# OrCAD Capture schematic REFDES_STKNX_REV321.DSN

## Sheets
1 P01 - Index: title: STKNX reference design; rev: 321; company: STMicroelectronics; note: Block diagram; note: 10 rue de Jouanet; note: 35700 Rennes, FR
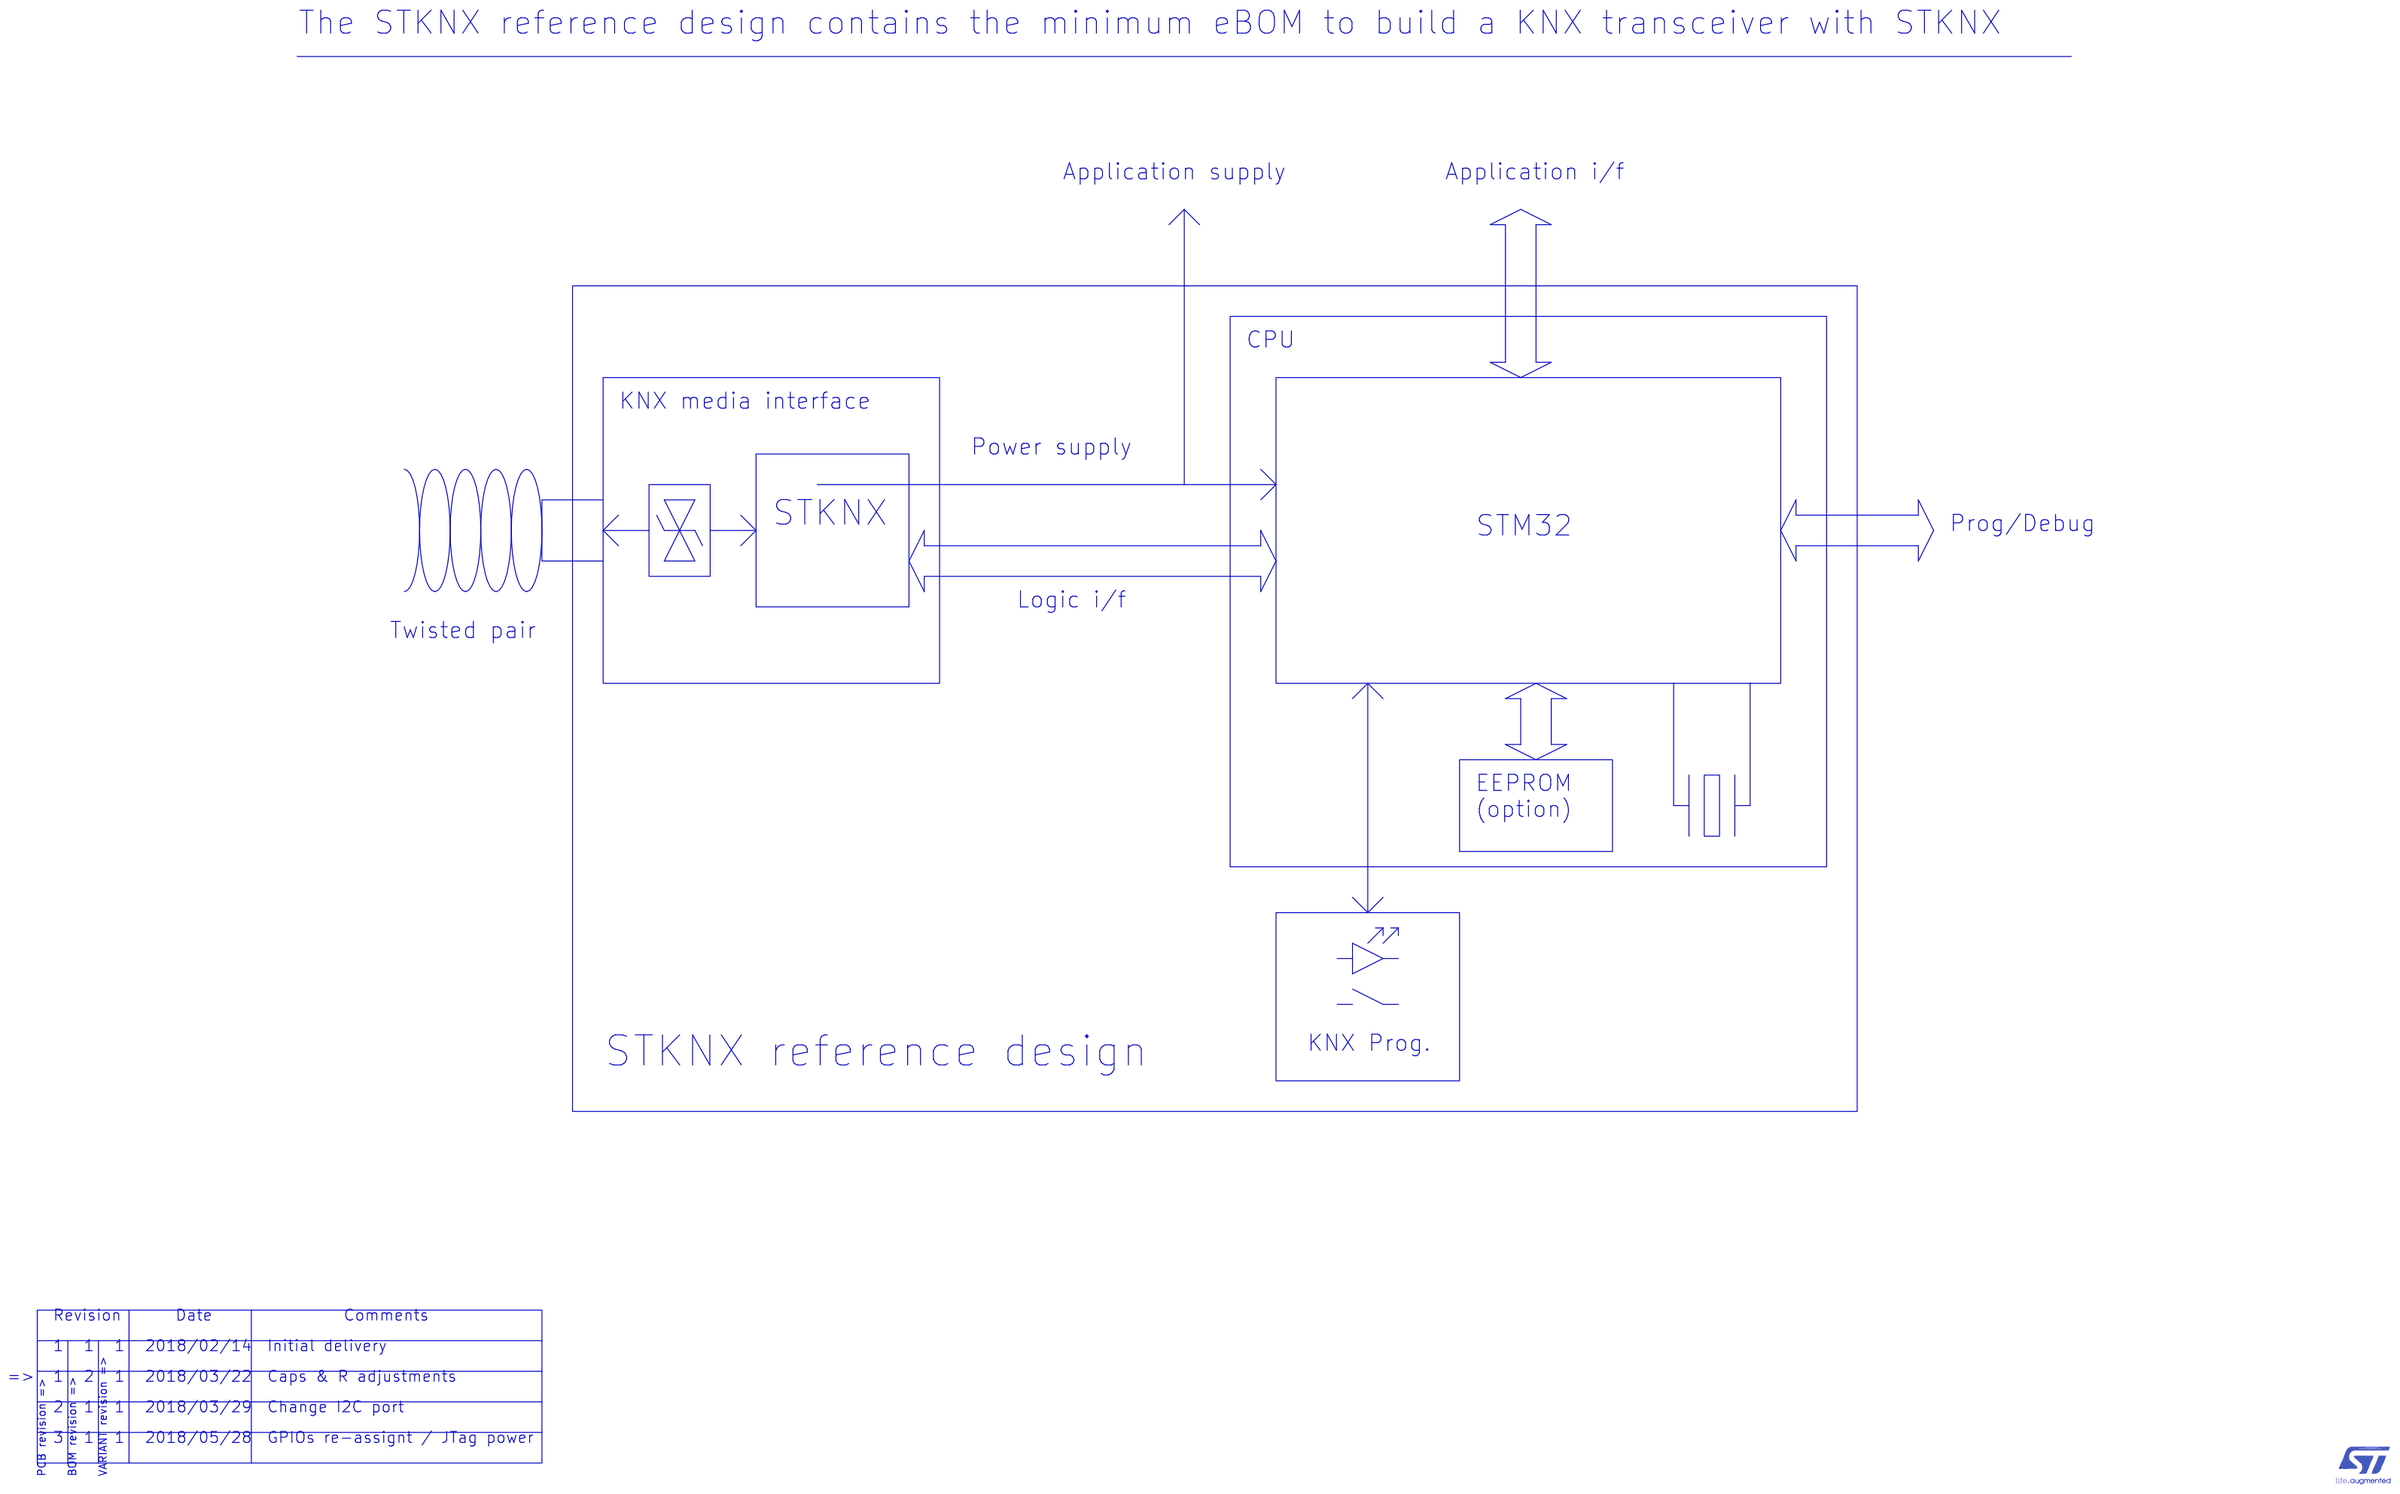
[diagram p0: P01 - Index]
2 P02 - STKNX: size A3; note: STKNX
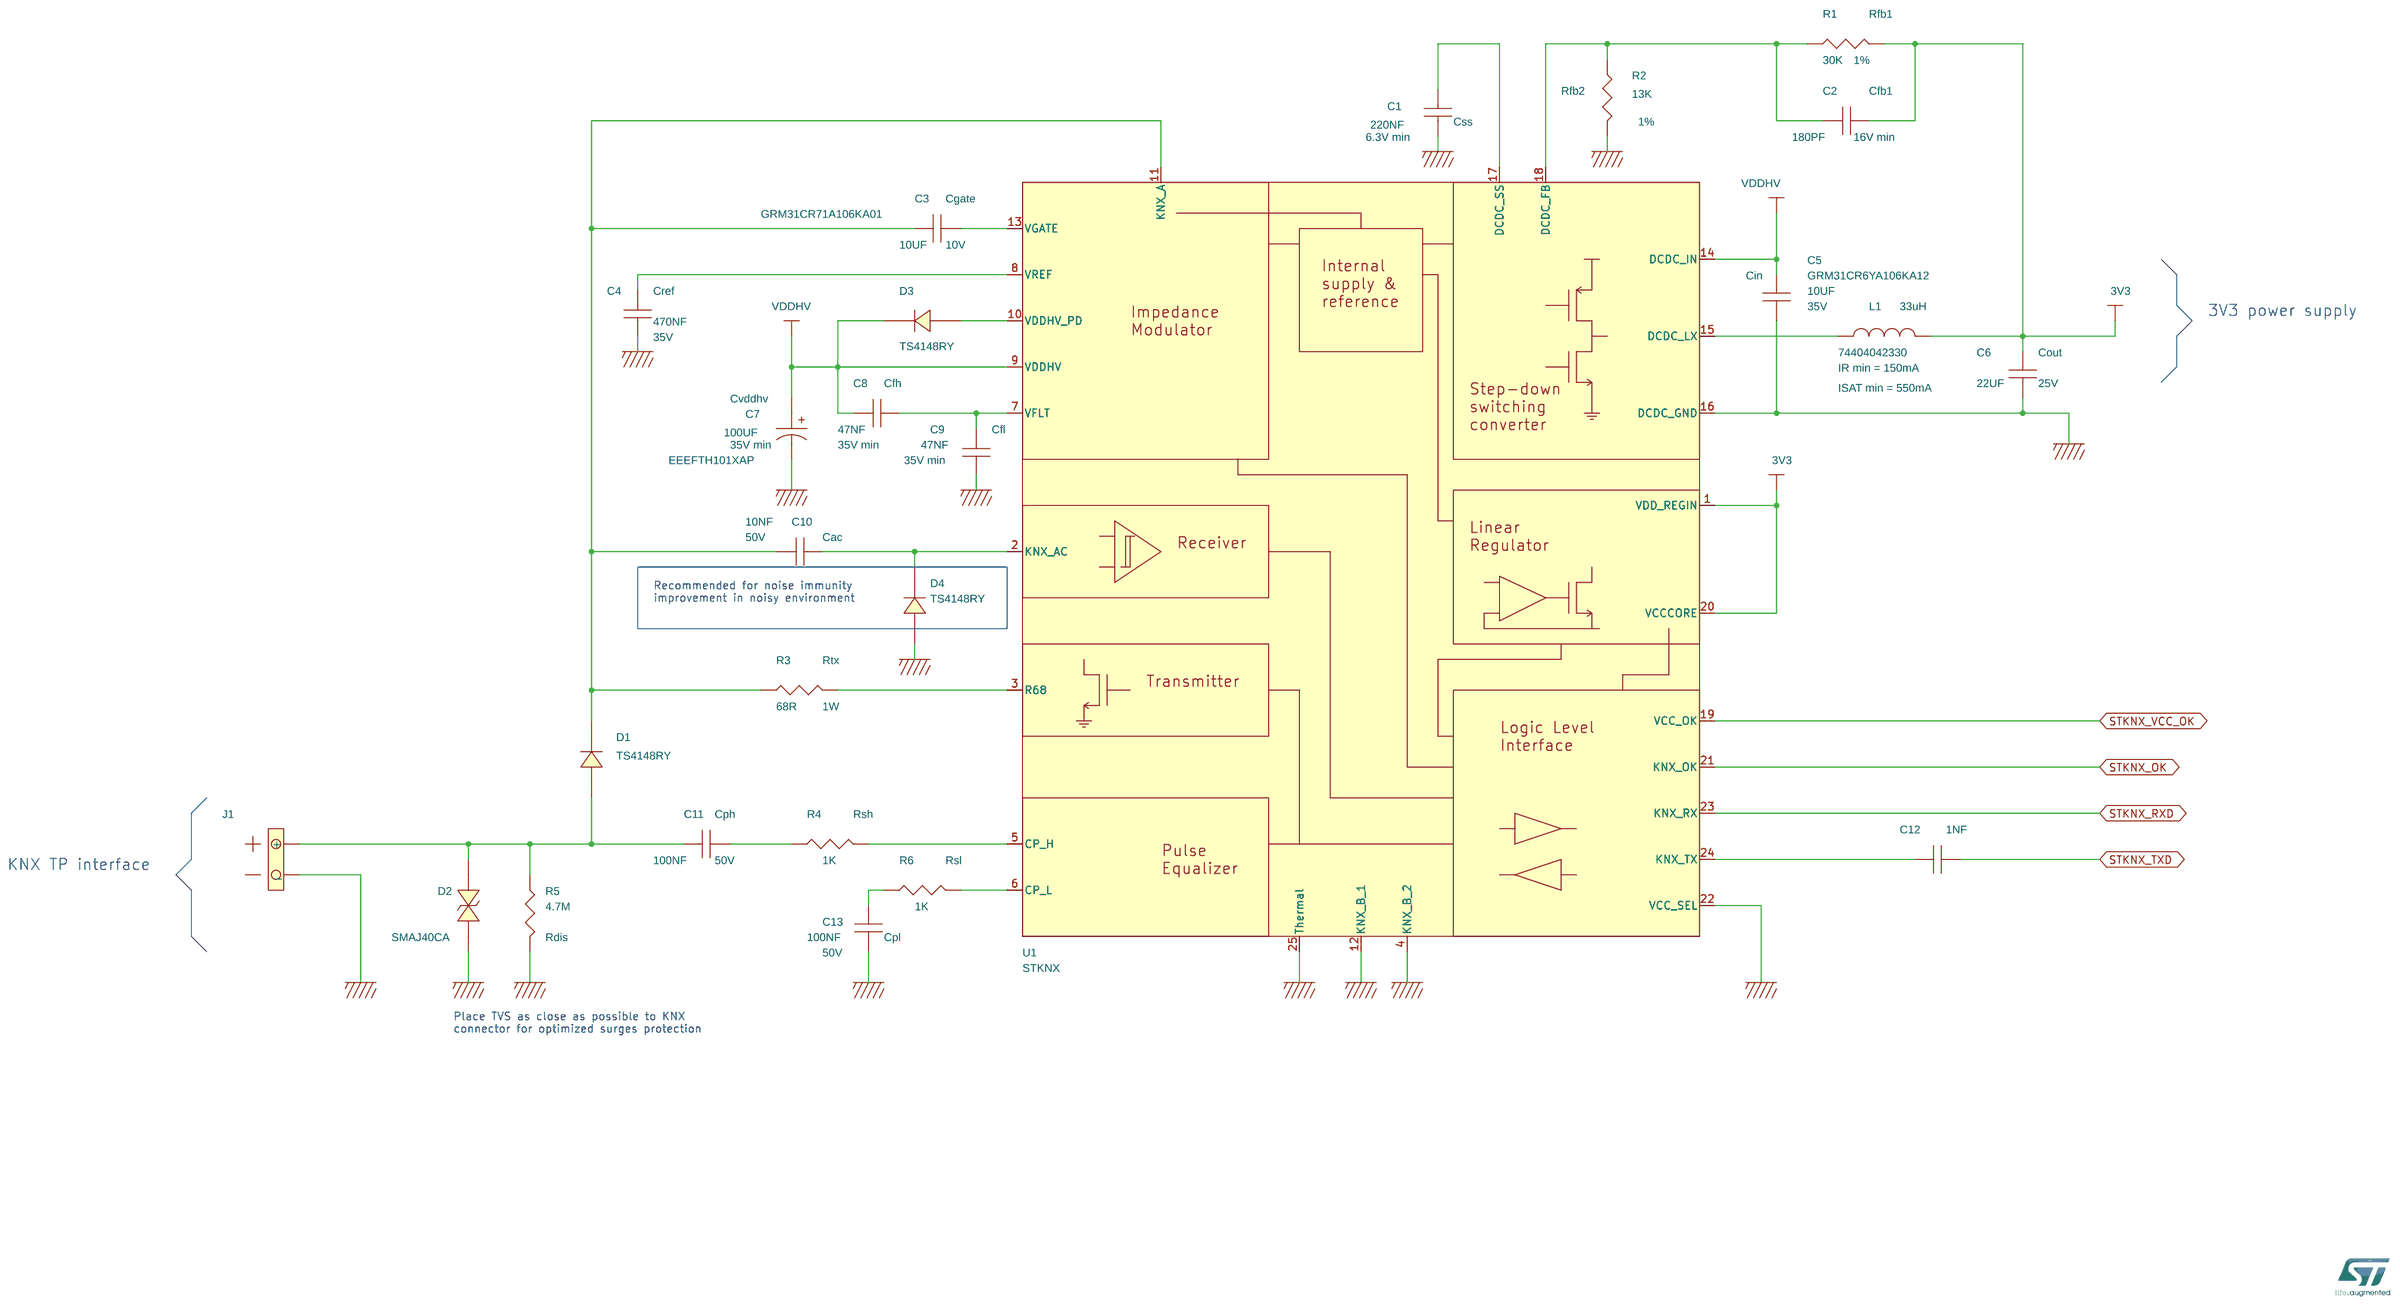
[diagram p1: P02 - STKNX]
3 P03 - CPU: size A3; note: CPU
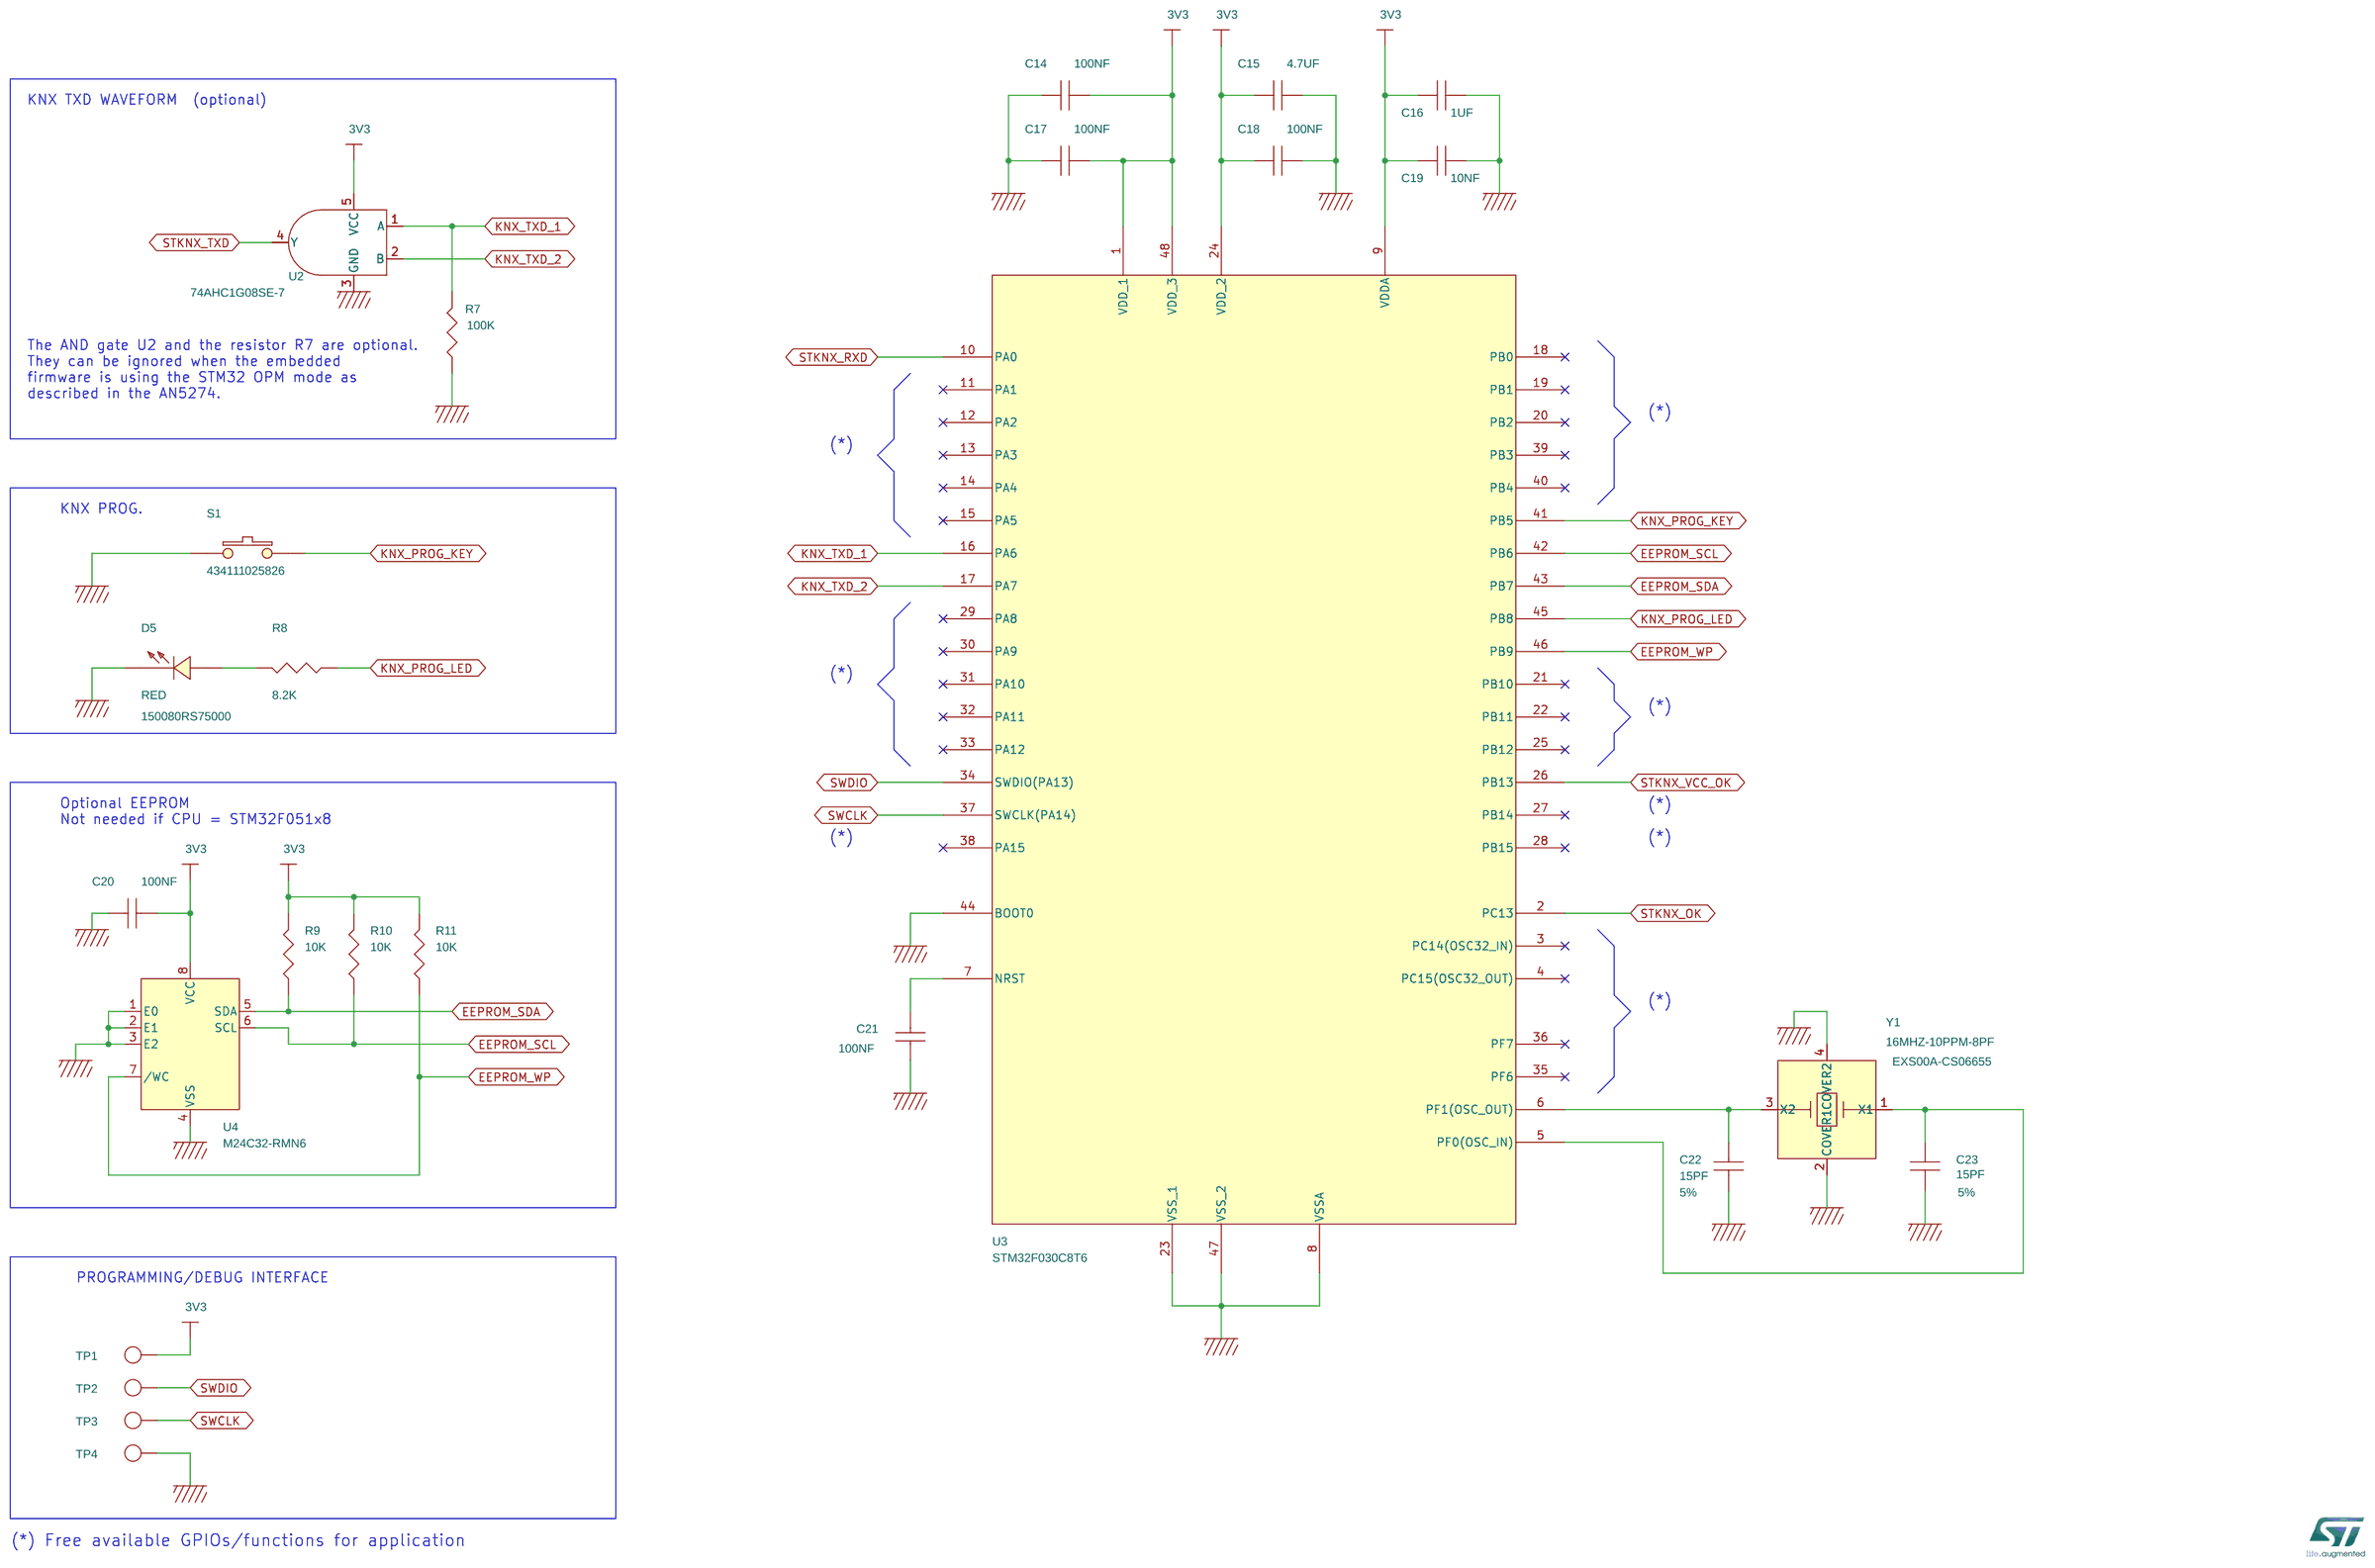
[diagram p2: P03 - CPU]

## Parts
sheet P02 - STKNX
C1  220NF  [0402]
C2  180PF  [0402]
C3  10UF  [1206]
C4  470NF  [0402]
C5  10UF  [1206]
C6  22UF  [1206]
C7  100UF  [D6.3_H7.7]
C8  47NF  [0402]
C9  47NF  [0402]
C10  10NF  [0402]
C11  100NF  [0402]
C12  1NF  [0402]
C13  100NF  [0402]
D1  TS4148RY  [0805]
D2  SMAJ40CA  [SMA]
D3  TS4148RY  [0805]
D4  TS4148RY  [0805]
J1  KNM1P5.75_2SQV80NE-T  [CON_KNM1P5.75_2SQV80NE-T]
L1  33uH  [L4_W4_H1.8]
R1  30K  [0402]
R2  13K  [0402]
R3  68R  [1218]
R4  1K  [0402]
R5  4.7M  [0402]
R6  1K  [0402]
U1  STKNX  [VFDFPN24_L4_W4_P0.5]
sheet P03 - CPU
C14  100NF  [0402]
C15  4.7UF  [0402]
C16  1UF  [0402]
C17  100NF  [0402]
C18  100NF  [0402]
C19  10NF  [0402]
C20  100NF  [0402]
C21  100NF  [0402]
C22  15PF  [0402]
C23  15PF  [0402]
D5  RED  [0805]
R7  100K  [0603]
R8  8.2K  [0402]
R9  10K  [0402]
R10  10K  [0402]
R11  10K  [0402]
S1  434111025826  [L6_W3.8_H2.5]
TP1  TPSMD-1MM  [Test Point]
TP2  TPSMD-1MM  [Test Point]
TP3  TPSMD-1MM  [Test Point]
TP4  TPSMD-1MM  [Test Point]
U2  74AHC1G08SE-7  [SOT353]
U3  STM32F030C8T6  [LQFP48]
U4  M24C32-RMN6  [SO8]
Y1  16MHZ-10PPM-8PF  [L2.0_W1.6_H0.45]

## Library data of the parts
C1 = C_CAP_NP: 220NF_6V3_X5R_0402; Datasheet label: Css; Manufacturer: MURATA; Minimum Voltage: 6.3V min; Part Number: GRM155R60J224KE01; Part Type: CER; Techno: CMS; Tolerance: 10%; Voltage: 6.3V
C2 = C_CAP_NP: 180PF_50V_COG_0402; Datasheet label: Cfb1; Manufacturer: MURATA; Minimum Voltage: 16V min; Part Number: GRM1555C1H181JA01; Part Type: CER; Techno: CMS; Tolerance: 5%; Voltage: 50V
C3 = C_CAP_NP: Chip Multilayer Ceramic Capacitors for General Purpose; Datasheet Link: http://psearch.en.murata.com/capacitor/product/GRM31CR71A106KA01%23.html; Datasheet label: Cgate; Distributor: RS; Distributor Part Number: 723-6559; Manufacturer: MURATA; Part Number: GRM31CR71A106KA01; Part Type: CER; Techno: X7R; Tolerance: 10%; Voltage: 10V
C4 = C_CAP_NP: 470NF_35V_X5R_0402; Datasheet label: Cref; Manufacturer: MURATA; Part Number: GRM155R6YA474KE01; Part Type: CER; Techno: CMS; Tolerance: 10%; Voltage: 35V
C5 = C_CAP_NP: Chip Multilayer Ceramic Capacitors for General Purpose; Datasheet Link: http://psearch.en.murata.com/capacitor/product/GRM188R6YA106MA73%23.html; Datasheet label: Cin; Distributor: RS; Distributor Part Number: 790-0613; Manufacturer: MURATA; Part Number: GRM31CR6YA106KA12; Part Type: CER; Techno: X5R; Tolerance: 10%; Voltage: 35V
C6 = C_CAP_NP: 22UF_25V_X5R_1206_20%; Datasheet label: Cout; Manufacturer: MURATA; Part Number: GRM32ER61E226KE15; Part Type: CER; Techno: CMS; Tolerance: 20%; Voltage: 25V
C7 = C_CAP_POL: 100uF Aluminum Electrolytic Capacitors High temperature Lead-Free reflow; Datasheet Link: https://fr.rs-online.com/web/p/condensateurs-aluminium/7296309/; Datasheet label: Cvddhv; Distributor: RS; Distributor Part Number: 729-6309; Layout Decal: CAPP_D6.3_PANA_D8; Manufacturer: PANASONIC; Minimum Voltage: 35V min; Part Number: EEEFTH101XAP; Part Type: ALU; Techno: CMS; Tolerance: 20%; Voltage: 50V
C8 = C_CAP_NP: 47NF_35V_X7R_0402; Datasheet label: Cfh; Manufacturer: MURATA; Minimum Voltage: 35V min; Part Number: GRM155R61H473KE19; Part Type: CER; Techno: CMS; Tolerance: 10%; Voltage: 35V
C9 = C_CAP_NP: 47NF_35V_X7R_0402; Datasheet label: Cfl; Manufacturer: MURATA; Minimum Voltage: 35V min; Part Number: GRM155R61H473KE19; Part Type: CER; Techno: CMS; Tolerance: 10%; Voltage: 35V
C10 = C_CAP_NP: 10NF_50V_X7R_0402; Datasheet label: Cac; Manufacturer: MURATA; Part Number: GRM155B31H103KA88; Part Type: CER; Techno: CMS; Tolerance: 10%; Voltage: 50V
C11 = C_CAP_NP: 100NF_50V_X7R_0402; Datasheet label: Cph; Manufacturer: MURATA; Part Number: GRM155R61H104KE14; Part Type: CER; Techno: CMS; Tolerance: 10%; Voltage: 50V
C12 = C_CAP_NP: 1NF_50V_X7R_0402; Manufacturer: MURATA; Part Number: GRM155R61H102KA01; Part Type: CER; Techno: CMS; Tolerance: 10%; Voltage: 50V
C13 = C_CAP_NP: 100NF_50V_X7R_0402; Datasheet label: Cpl; Manufacturer: MURATA; Part Number: GRM155R61H104KE14; Part Type: CER; Techno: CMS; Tolerance: 10%; Voltage: 50V
D1 D3 D4 = D_DIODE: 0.5AMPS High Speed Switching Diode; Datasheet Link: http://www.mouser.com/ds/2/395/taiwansemiconductor_TS4148RY-553424.pdf; Distributor: MOUSER; Distributor Part Number: 821-TS4148-0805-RY; Layout Decal: LED_0805; Manufacturer: TAIWAN SEMICONDUCTOR; Part Type: SCHOTTKY
D2 = D_DIODE_TVS_BI: Bi-Directional TVS Diode, 400W, 2-Pin SMA; Datasheet Link: http://www.st.com/content/ccc/resource/technical/document/datasheet/ff/c0/80/cc/19/4c/45/af/CD00001333.pdf/files/CD00001333.pdf/jcr:content/translations/en.CD00001333.pdf; Distributor: RS; Distributor Part Number: 714-7109; Layout Decal: SMA_BIDIR; Manufacturer: STMICROELECTRONICS; Part Type: TVS
J1 = J_KNX-Male: KNX BENT PCB HEADER 2P TYPE KNM1 PITCH 5.75mm VERSION SQ; Datasheet Link: \\gnx5948.gnb.st.com\RNS_IPC\2_PROJECT_IPC\_Datasheets\Connectors\BOARD TO CABLE\KNX\Stelvio-Kontek-WE; Manufacturer: WURTH ELEKTRONIK STELVIO-KONTEK; Part Type: HEADER
L1 = L_INDUCTOR: WE-LQS SMD Power Inductor; Current: 0,65A; Datasheet Link: https://katalog.we-online.de/pbs/datasheet/74404042330.pdf; Distributor: RS; Distributor Part Number: 814-2537; IR min: 150mA; ISAT min: 550mA; Layout Decal: IND-WE-LQS; Manufacturer: WURTH ELEKTRONIK; Part Number: 74404042330; Part Type: INDUCTOR; Techno: CMS; Tolerance: 20%
R1 = R_R: Generic resistor 30 kOhm 0402 1%; Datasheet label: Rfb1; Part Number: 30K_1%_0402; Part Type: RES; Power: 1/16W; Techno: CMS; Tolerance: 1%
R2 = R_R: Generic resistor 13 kOhm 0402 1%; Datasheet label: Rfb2; Part Number: 13K_1%_0402; Part Type: RES; Power: 1/16W; Techno: CMS; Tolerance: 1%
R3 = R_R: Generic Resistor 68 Ohm 1218 1W; Datasheet label: Rtx; Part Number: 68R_5%_1218_1W; Part Type: RES; Power: 1W; Techno: CMS; Tolerance: 5%
R4 = R_R: Generic resistor 0402; Datasheet label: Rsh; Part Number: 1K_5%_0402; Part Type: RES; Power: 1/16W; Techno: CMS; Tolerance: 5%
R5 = R_R: Generic Resistor 4.7 MOhm 0402; Datasheet label: Rdis; Part Number: 4.7M_5%_0402; Part Type: RES; Power: 1/16W; Techno: CMS; Tolerance: 5%
R6 = R_R: Generic resistor 0402; Datasheet label: Rsl; Part Number: 1K_5%_0402; Part Type: RES; Power: 1/16W; Techno: CMS; Tolerance: 5%
U1 = U_STKNX: KNX XCVR Twisted Pair; Datasheet Link: \\gnx5948.gnb.st.com\RNS_IPC\2_PROJECT_IPC\IA-4-KNX\300-Platforms\200-STKITT\2-ASIC\1-Doc\Datasheet; Layout Decal: QFN24_L4_W4_P0.5; Manufacturer: STMICROELECTRONICS; Part Type: TRANSCEIVER; Sub Type: KNX
C14 C17 C18 C20 C21 = C_CAP_NP: 100NF_6V3_X5R_0402_10%; Manufacturer: MURATA; Part Number: GRM155R60J104KA01; Part Type: CER; Techno: CMS; Tolerance: 10%; Voltage: 6.3V
C15 = C_CAP_NP: 4.7UF_6V3_X5R_0402_20%; Manufacturer: MURATA; Part Number: GRM155R60J475ME47; Part Type: CER; Techno: CMS; Tolerance: 20%; Voltage: 6.3V
C16 = C_CAP_NP: 1UF_6V3_X5R_0402; Manufacturer: MURATA; Part Number: GRM152R60J105ME15; Part Type: CER; Techno: CMS; Tolerance: 10%; Voltage: 6.3V
C19 = C_CAP_NP: Generic capacitor 10nF 0402 6V3; Part Number: 10NF_6V3_X5R_0402_10%; Part Type: CER; Techno: X5R; Tolerance: 10%; Voltage: 6.3V
C22 C23 = C_CAP_NP: CAP CER 15PF 50V C0G/NP0 0402; Datasheet Link: https://www.digikey.com/product-detail/en/murata-electronics-north-america/GRM1555C1H150JA01J/490-11376-2-ND/4420268; Distributor: DIGIKEY; Distributor Part Number: 490-11376-2-ND; Manufacturer: MURATA; Part Number: GRM1555C1H150JA01; Part Type: CER; Techno: C0G; Tolerance: 5%; Voltage: 50V
D5 = D_LED: VF=2V - IF=30mA; Datasheet Link: http://katalog.we-online.de/led/datasheet/150080RS75000.pdf; Distributor: RS; Distributor Part Number: 815-4225; Layout Decal: LED_0805; Manufacturer: WURTH ELEKTRONIK; Part Number: 150080RS75000; Part Type: LED
R7 = R_R: Generic Resistor 100 kOhm 0603; Part Number: 100K_5%_0603; Part Type: RES; Power: 1/10W; Techno: CMS; Tolerance: 5%
R8 = R_R: Generic Resistor 8.2 kOhm 0402; Part Number: 8.2K_5%_0402; Part Type: RES; Power: 1/16W; Techno: CMS; Tolerance: 5%
R9-R11 = R_R: Generic Resistor 10 kOhm 0402; Part Number: 10K_5%_0402; Part Type: RES; Power: 1/16W; Techno: CMS; Tolerance: 5%
S1 = S_BUTTON_2PINS_1-2: White Tact Switch, NO 50 mA@ 12 V dc 0.8mm Surface Mount; Datasheet Link: http://fr.rs-online.com/web/p/interrupteurs-tactiles/7856406/; Distributor: RS; Distributor Part Number: 785-6406; Layout Decal: BUTTON_L6_W3.8_2PINS; Manufacturer: WURTH ELEKTRONIK; Part Type: BUTTON
TP1-TP4 = TP_TPSMD-40RD: Point Test PCB 1MM DIAMETER; Part Type: TEST POINT
U2 = U_SN74AHC1G08: IC GATE AND 1CH 2-INP SOT-353; Datasheet Link: https://www.digikey.com/product-detail/en/diodes-incorporated/74AHC1G08SE-7/74AHC1G08SE-7DITR-ND/2639242; Distributor: DIGIKEY; Distributor Part Number: 74AHC1G08SE-7DITR-ND; Manufacturer: DIODES INC; Part Type: LOGIC; Sub Type: GATE
U3 = U_STM32F030C8Tx_LQFP48: 32bit ARM Cortex M0 Microcontroller, 48MHz, 64 kB Flash, 48-Pin LQFP; Datasheet Link: https://fr.rs-online.com/web/p/microcontroleurs/7925921/; Distributor: RS; Distributor Part Number: 792-5921; Manufacturer: STMICROELECTRONICS; Part Type: MCU; Sub Type: 32 Bits
U4 = U_M24C32-8pins: IC EEPROM 32KBIT 400KHZ 8SO; Datasheet Link: https://www.digikey.com/product-detail/en/stmicroelectronics/M24C32-RMN6TP/497-8644-2-ND/1663601; Distributor: DIGIKEY; Distributor Part Number: 497-8644-2-ND; Manufacturer: STMICROELECTRONICS; Part Type: MEMORY; Sub Type: EEPROM
Y1 = Y_XTAL_4PINS_QUATER: SMD crystal; Datasheet Link: W:\2_PROJECT_IPC\_Datasheets\Xtals\QUARTZ\ST-MICROELECTRONICS NX2016SA 16MHz EXS00A-CS06655  (EXS10B-18812D).pdf; Layout Decal: XTAL_L2.0_W1.6_4PINS; Manufacturer: NDK; Part Number: EXS00A-CS06655; Part Type: QUARTZ

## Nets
3V3: C2.1 C6.1 C14.2 C15.1 C16.1 C17.2 C18.1 C19.1 C20.2 L1.2 R1.2 R9.2 R10.2 R11.2 TP1.1 U1.1(VDD_REGIN) U1.20(VCCCORE) U2.5(VCC) U3.1(VDD) U3.9(VDDA) U3.24(VDD_2) U3.48(VDD_3) U4.8(VCC)
GND_KIT: C1.2 C4.1 C5.2 C6.2 C7.2 C9.1 C13.2 C14.1 C15.2 C16.2 C17.1 C18.2 C19.2 C20.1 C21.1 C22.2 C23.2 D2.1 D4.A D5.K J1.2(_) R2.1 R5.2 R7.1 S1.2 TP4.1 U1.4(KNX_B_2) U1.12(KNX_B_1) U1.16(DCDC_GND) U1.22(VCC_SEL) U1.25(Thermal) U2.3(GND) U3.8(VSSA) U3.23(VSS_1) U3.44(BOOT0) U3.47(VSS_2) U4.1(E0) U4.2(E1) U4.3(E2) U4.4(VSS) Y1.2(COVER1) Y1.4(COVER2)
VDDHV: C5.1 C7.1 C8.2 D3.K U1.9(VDDHV) U1.14(DCDC_IN)
EEPROM_SCL: R10.1 U3.42(PB6) U4.6(SCL)
EEPROM_SDA: R9.1 U3.43(PB7) U4.5(SDA)
EEPROM_WP: R11.1 U3.46(PB9) U4.7(/WC)
KNX_PROG_KEY: S1.1 U3.41(PB5)
KNX_PROG_LED: R8.1 U3.45(PB8)
KNX_TXD_1: R7.2 U2.1(A) U3.16(PA6)
KNX_TXD_2: U2.2(B) U3.17(PA7)
STKNX_OK: U1.21(KNX_OK) U3.2(PC13)
STKNX_RXD: U1.23(KNX_RX) U3.10(PA0)
STKNX_TXD: C12.2 U2.4(Y)
STKNX_VCC_OK: U1.19(VCC_OK) U3.26(PB13)
SWCLK: TP3.1 U3.37(SWCLK(PA14))
SWDIO: TP2.1 U3.34(SWDIO(PA13))
N18218192: C13.1 R6.1
N18218250: R6.2 U1.6(CP_L)
N18222497: C3.2 U1.13(VGATE)
N18222503: C3.1 C10.2 D1.K R3.1 U1.11(KNX_A)
N18222555: C10.1 D4.K U1.2(KNX_AC)
N18222626: R3.2 U1.3(R68)
N18222726: C11.2 R4.1
N18222728: C11.1 D1.A D2.2 J1.1(+) R5.1
N18222764: R4.2 U1.5(CP_H)
N18222990: D3.A U1.10(VDDHV_PD)
N18223050: C8.1 C9.2 U1.7(VFLT)
N18223434: L1.1 U1.15(DCDC_LX)
N18224142: C1.1 U1.17(DCDC_SS)
N18228378: C2.2 R1.1 R2.2 U1.18(DCDC_FB)
N18229442: C4.2 U1.8(VREF)
N18389644: C21.2 U3.7(NRST)
N18401705: D5.A R8.2
N18403083: C22.1 U3.6(PF1(OSC_OUT)) Y1.3(X2)
N18403207: C23.1 U3.5(PF0(OSC_IN)) Y1.1(X1)
N18409787: C12.1 U1.24(KNX_TX)

Not connected (* = marked no-connect by the designer): U3 3(PC14(OSC32_IN))* 4(PC15(OSC32_OUT))* 11(PA1)* 12(PA2)* 13(PA3)* 14(PA4)* 15(PA5)* 18(PB0)* 19(PB1)* 20(PB2)* 21(PB10)* 22(PB11)* 25(PB12)* 27(PB14)* 28(PB15)* 29(PA8)* 30(PA9)* 31(PA10)* 32(PA11)* 33(PA12)* 35(PF6)* 36(PF7)* 38(PA15)* 39(PB3)* 40(PB4)*

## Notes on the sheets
sheet 1
- The STKNX reference design contains the minimum eBOM to build a KNX transceiver with STKNX
- Application supply
- Application i/f
- CPU
- KNX media interface
- Power supply
- STKNX
- STM32
- Prog/Debug
- Logic i/f
- Twisted pair
- EEPROM
  (option)
- STKNX reference design
- KNX Prog.
- Revision
- Date
- Comments
- 1
- 1
- 1
- 2018/02/14
- Initial delivery
- =>
- 1
- 2
- 1
- 2018/03/22
- Caps & R adjustments
- 2
- 1
- 1
- 2018/03/29
- Change I2C port
- 3
- 1
- 1
- 2018/05/28
- GPIOs re-assignt / JTag power
- PCB revision =>
- BOM revision =>
- VARIANT revision =>
sheet 2
- 3V3 power supply
- Recommended for noise immunity
  improvement in noisy environment
- KNX TP interface
- Place TVS as close as possible to KNX
  connector for optimized surges protection
sheet 3
- KNX TXD WAVEFORM  (optional)
- The AND gate U2 and the resistor R7 are optional.
  They can be ignored when the embedded
  firmware is using the STM32 OPM mode as
  described in the AN5274.
- (*)
- (*)
- KNX PROG.
- (*)
- (*)
- Optional EEPROM
  Not needed if CPU = STM32F051x8
- (*)
- (*)
- (*)
- (*)
- PROGRAMMING/DEBUG INTERFACE
- (*) Free available GPIOs/functions for application
